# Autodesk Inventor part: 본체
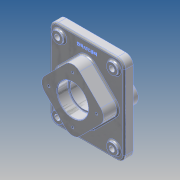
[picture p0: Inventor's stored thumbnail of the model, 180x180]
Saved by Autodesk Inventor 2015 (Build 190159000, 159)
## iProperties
Created: 2026-07
Part Number: 본체
Material: 알루미늄 6061
Document SubType Name: Modeling
Designer: USER
Density: 2.7 g/cm^3
Appearance: 알루미늄 - 평지
Mass: 2132.41 g
Surface Area: 955.114 cm^2
Volume: 789.782 cm^3
Author: USER
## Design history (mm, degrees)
sketch "스케치1"
  geometry: L1 (0, 70.711)-(-70.711, 0); L2 (-70.711, 0)-(0, -70.711); L3 (0, -70.711)-(70.711, 0); L4 (70.711, 0)-(0, 70.711); L5 (75, 90)-(-75, 90); L6 (-75, 90)-(-75, -90); L7 (-75, -90)-(75, -90); L8 (75, -90)-(75, 90); L9 (75, 90)-(-75, -90); L10 (-75, 90)-(75, -90); 3 further points
  constraints: 20 end point, 4 midpoint, 4 parallel, 2 perpendicular, 2 vertical alignment, 1 horizontal, 1 horizontal alignment
  dimensions: "d6" = 100 distance of L1.start L1.end; "d8" = 100 distance between parallel lines of L1 L3; "d9" = 150 distance of L5.start L5.end; "d10" = 180 distance of L7.end L5.start
extrude "돌출1" new body sketch "스케치1" distance "d11" = 23; taper "d12" = 0 deg
extrude "돌출2" join sketch "스케치1" distance "d13" = 18; taper "d14" = 0 deg
sketch "스케치2"
  geometry: L1 (-75, 90)-(75, -90) reference; L2 (0, 70.711)-(70.711, 0) reference; L3 (70.711, 0)-(0, -70.711) reference; L4 (0, -70.711)-(-70.711, 0) reference; L5 (-70.711, 0)-(0, 70.711) reference; 1 further point
extrude "돌출3" join sketch "스케치2" distance "d15" = 29; taper "d16" = 0 deg
fillet "모깎기1" dims "d17" = 20
sketch "스케치3"
  geometry: C1 r 31 at (0, 0); 1 further point
  constraints: 1 centre point, 1 coincident
  dimensions: "d18" = 62 diameter of C1
extrude "돌출4" cut sketch "스케치3" distance "d19" = 22; taper "d20" = 0 deg
sketch "스케치4"
  geometry: C1 r 31 at (0, 0); 1 further point
  constraints: 1 centre point, 1 coincident
  dimensions: "d21" = 62 diameter of C1
extrude "돌출5" cut sketch "스케치4" distance "d22" = 22; taper "d23" = 0 deg
hole "구멍1" diameter "d26" = 54; stored, may be unused: countersink angle "d30" = 90 deg, drill point angle "d32" = 118 deg; dims "d24" = 10, "d25" = 10, "d27" = 6, "d28" = 4, "d29" = 2, "d31" = 8
fillet "모깎기2" dims "d33" = 15
sketch "스케치5"
  geometry: L1 (0, 0)-(48, 0)
  constraints: 2 end point, 1 horizontal
  dimensions: "d34" = 48 distance of L1.start L1.end
hole "구멍2" sketch "스케치5" at (48, 0) diameter "d35" = 4.917; stored, may be unused: countersink angle "d39" = 90 deg, drill point angle "d41" = 118 deg; dims "d36" = 10, "d37" = 4, "d38" = 2, "d40" = 13
node "작업 평면1"
sketch "스케치6"
  geometry: L1 (75, -75)-(75, 75) reference; L2 (60, 90)-(-60, 90) reference; C1 r 11 at (55, 70); 1 further point
  constraints: 1 centre point
  dimensions: "d45" = 22 diameter of C1; "d46" = 20 distance from line of L1 C1.centre; "d47" = 20 distance from line of L2 C1.centre
extrude "돌출6" join sketch "스케치6" distance "d48" = 5; taper "d49" = 0 deg
hole "구멍3" diameter "d52" = 11; stored, may be unused: countersink angle "d56" = 90 deg, drill point angle "d58" = 0 deg; dims "d50" = 10, "d51" = 10, "d53" = 11, "d54" = 4, "d55" = 2, "d57" = 13
sketch "스케치7"
  geometry: L1 (60, 90)-(-60, 90) reference; 2 further points
  constraints: 1 vertical alignment, 1 other
  dimensions: "d65" = 15 distance from line of point (0, 75) L1
feature "엠보싱1" sketch "스케치7" dims "d6" = 100, "d8" = 100, "d9" = 150, "d10" = 180, "d66" = 0.5, "d67" = 0
fillet "모깎기3" dims "d68" = 1
chamfer "모따기1" distance "d69" = 1; stored, may be unused: second distance "d70" = 2, angle "d71" = 45 deg
fillet "모깎기4" dims "d72" = 3
fillet "모깎기5" dims "d73" = 3
fillet "모깎기6" dims "d74" = 3
node "솔리드1"
pattern_circular "원형 패턴1" dims angle "d43" = 360 deg
mirror "대칭1"
pattern_linear "직사각형 패턴1"
node "투영된 루프1"
